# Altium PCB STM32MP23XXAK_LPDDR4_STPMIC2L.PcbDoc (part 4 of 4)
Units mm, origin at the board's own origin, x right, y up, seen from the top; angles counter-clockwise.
Board outline 120 x 79.6 mm, 4 copper layers (Top Layer, Signal Layer 1, Signal Layer 2, Bottom Layer), stack 1.614 mm thick; 156 components, 124 nets, 1131 pads, 692 vias.
Unrouted connection lines stored in the file: 3.
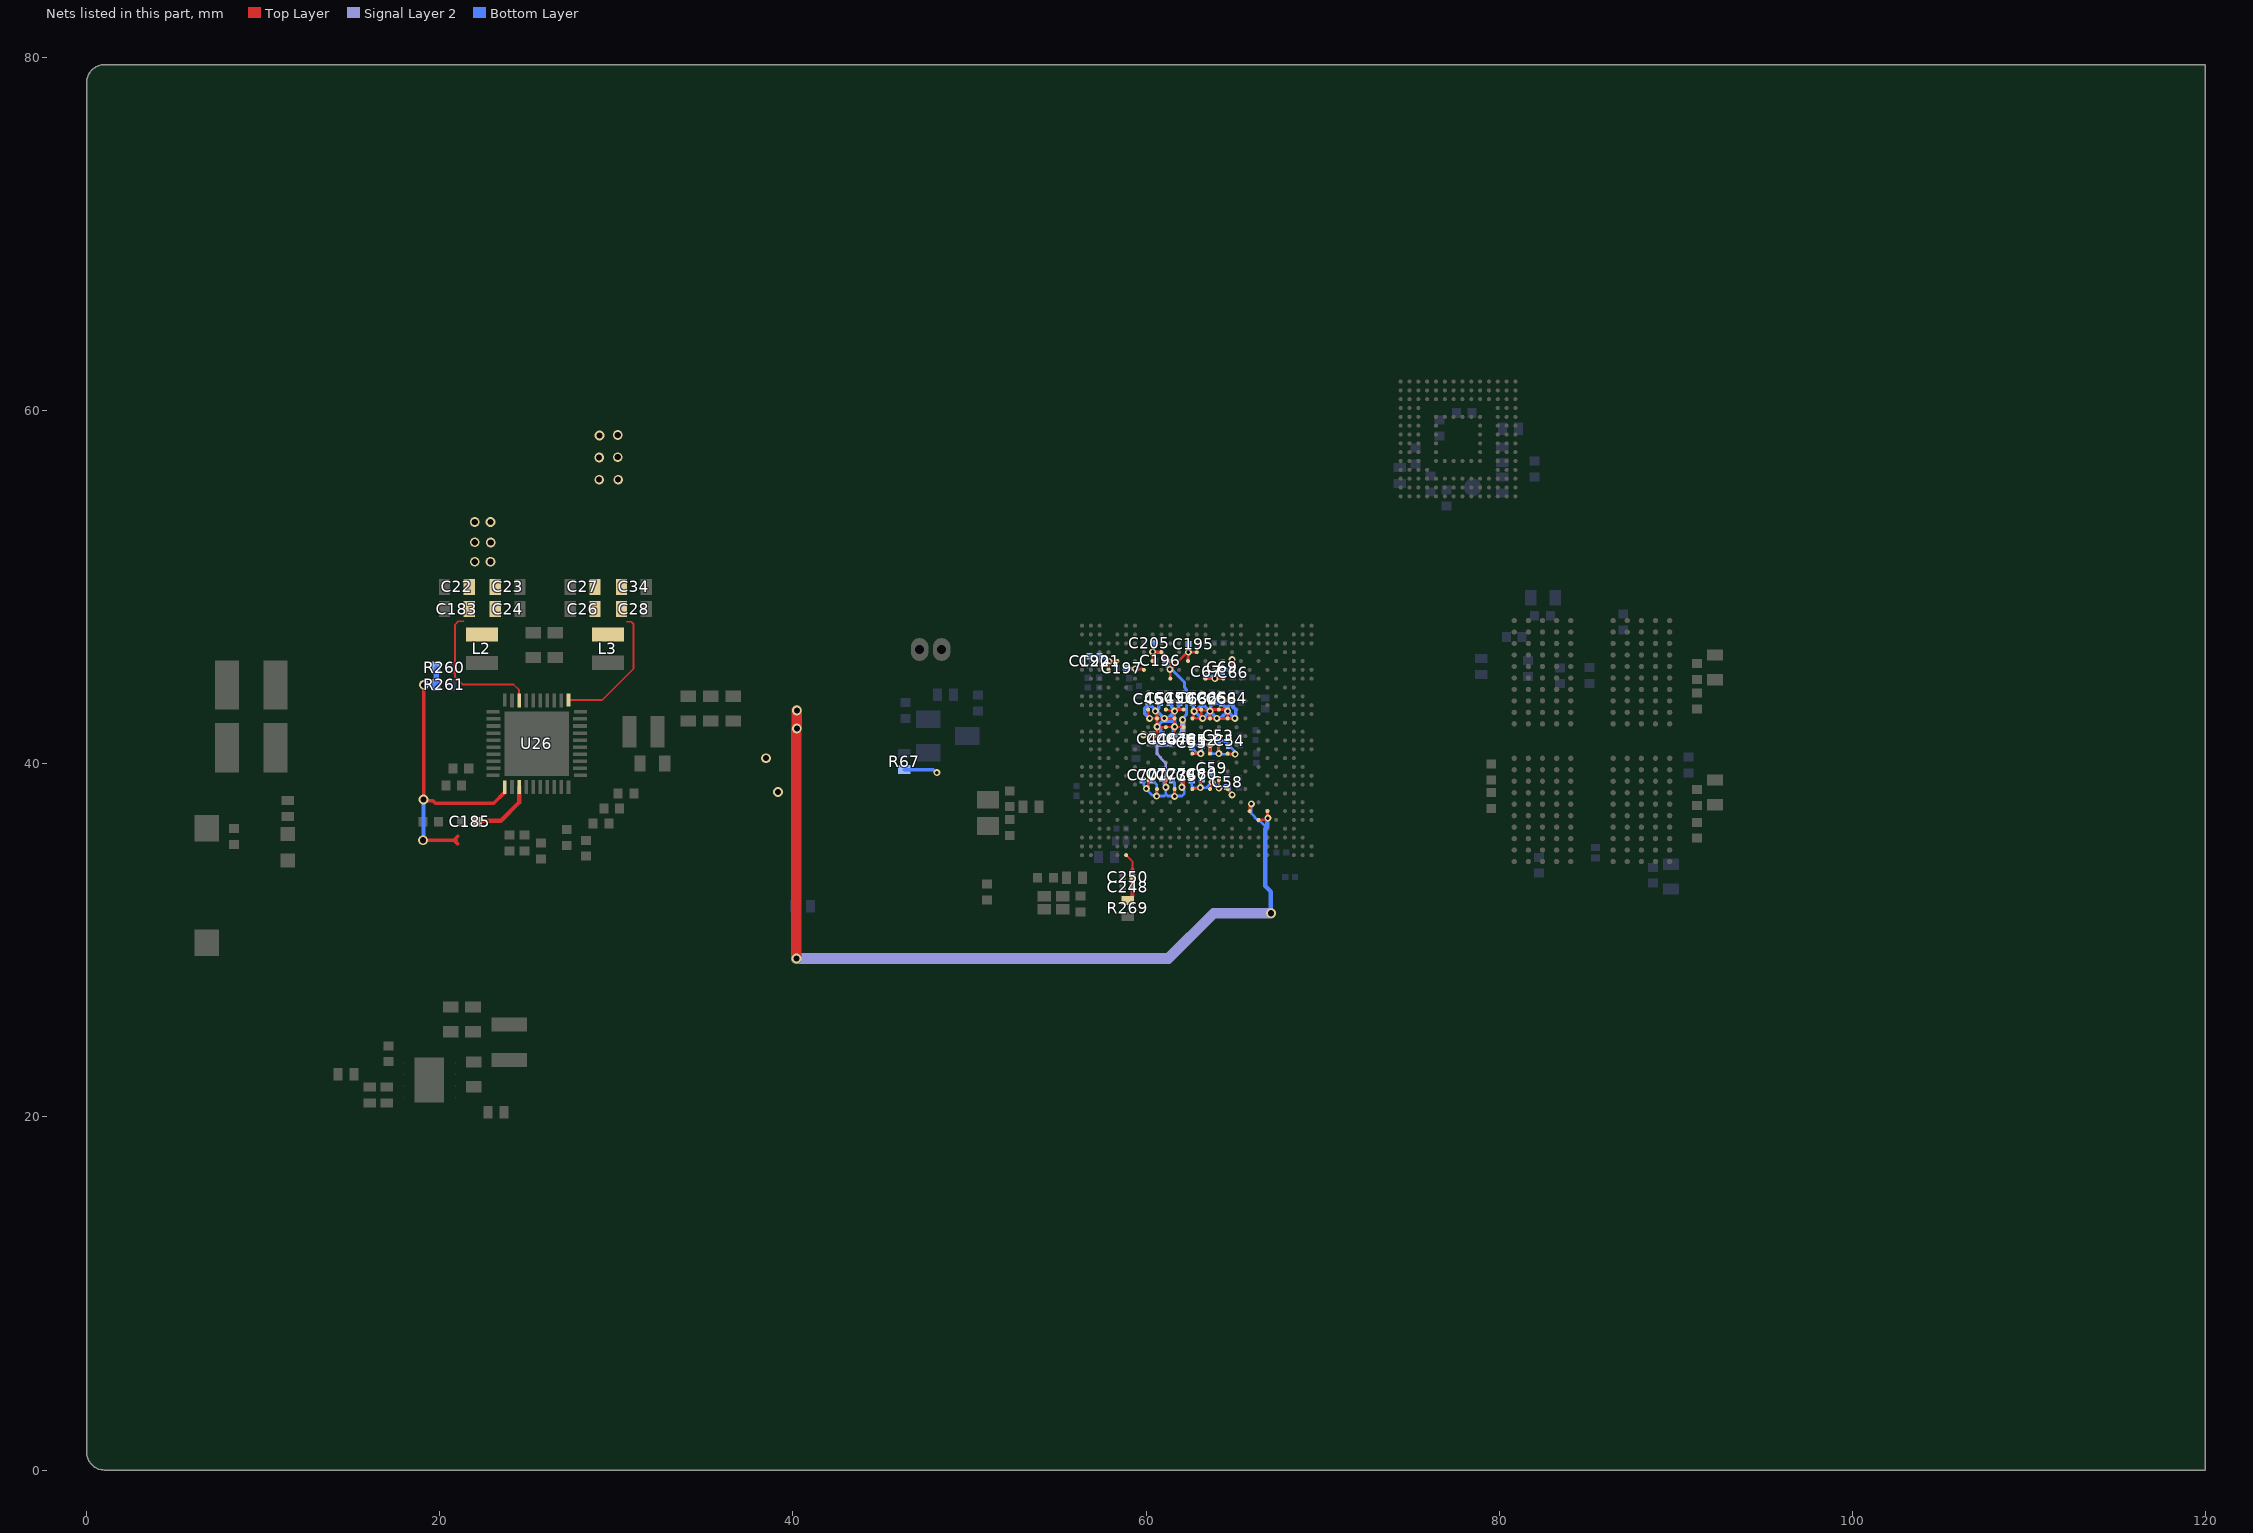
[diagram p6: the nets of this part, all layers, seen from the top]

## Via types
v1: diameter 0.55, hole 0.35, Top Layer to Bottom Layer, 364 vias
v2: diameter 0.4, hole 0.2, Top Layer to Bottom Layer, tented both sides, 223 vias
v3: diameter 0.4, hole 0.2, Top Layer to Bottom Layer, 105 vias

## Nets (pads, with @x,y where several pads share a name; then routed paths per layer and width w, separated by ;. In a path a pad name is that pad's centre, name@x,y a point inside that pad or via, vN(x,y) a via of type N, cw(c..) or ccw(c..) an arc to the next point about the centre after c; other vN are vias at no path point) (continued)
VDDCORE: C22.2 C23.2 C24.2 C44.1 C45.2 C46.2 C47.1 C48.2 C49.2 C50.2 C51.2 C183.2 C192.2 C197.2 C201.2 L2.2 U1.1C1 U1.1C3 U1.1C5 U1.1D2 U1.1D4 U1.1E3 U1.1E5 U1.1F2 U1.1F4 U1.AB20 U1.AB22 U1.AC21 U1.E5 U1.F4 U1.F8 U26.18 | length 80.3
  Top Layer w0.1: 21.35,48.075 21.05,48.075 20.857,47.882 20.857,44.927 21.288,44.495 24.174,44.495 24.488,44.181 U26.18@24.488,43.594
  Top Layer w0.15: U1.F4@57.875,45.325 v2(57.9,45.8) U1.E5@58.375,45.825 ; v2(59.4,45.375) 59.803,45.375 59.853,45.325 U1.F8@59.875,45.325 ; v2(59.85,41.65) 59.904,41.65 59.981,41.573 U1.1F2@60.624,41.573 ; U1.1C1@60.125,43.075 60.125,42.724 60.206,42.643 v2@60.206,42.575 ; v2(60.21,42.575) U1.1D2@60.625,42.575 ; v2@60.545,42.99 60.545,42.922 60.625,42.842 U1.1D2@60.625,42.575 ; U1.1F2@60.625,41.65 v2(60.625,42.1) ; U1.1C3@61.125,43.075 v2(61.625,42.983) ; U1.1F4@61.625,41.575 v2(61.625,42.1) ; U1.1E5@62.125,42.075 v2(61.625,42.1) ; U1.1C5@62.125,43.075 61.771,43.075 61.679,42.983 v2(61.625,42.983) ; U1.AB20@65.875,37.325 65.875,37.607 65.95,37.682 v2@65.95,37.75 ; U1.AC21@66.375,36.825 66.8,36.825 v2@66.888,36.913 ; v2(60.625,42.1) U1.1D2@60.625,42.575 ; v2(60.625,42.1) 60.65,42.075 U1.1E3@61.125,42.075 v2(61.625,42.1) ; U1.1D2@60.625,42.575 61.017,42.572 61.622,42.572 U1.1D4@61.625,42.575 ; v2(61.625,42.1) U1.1D4@61.625,42.575 ; U1.1D4@61.625,42.575 v2@61.625,42.983
  Top Layer w0.16: U1.AB22@66.875,37.325 66.875,36.95 v2(66.9,36.925)
  Top Layer w0.6: v1(40.2,28.975) 40.2,41.975 v1(40.225,42) v1(40.225,43.025)
  Signal Layer 2 w0.6: v1(40.2,28.975) 61.257,28.974 63.827,31.544 66.413,31.544 66.415,31.542 v1(67.078,31.542)
  Bottom Layer w0.15: v2(65.969,37.735) 65.95,37.716 65.95,37.205 66.167,36.988 66.167,36.95 66.367,36.75 66.466,36.75 66.821,36.395
  Bottom Layer w0.2: C192.2@56.8,46.1 C201.2@57.375,46.1 57.45,46.025 57.675,46.025 v2(57.9,45.8) ; C197.2@58.755,45.355 58.775,45.375 v2(59.4,45.375) ; v2(59.85,41.65) 60.346,41.65 C44.1@60.351,41.655 ; v2@60.206,42.575 59.942,42.839 59.942,43.153 60.059,43.27 60.098,43.27 60.173,43.345 60.198,43.32 60.235,43.32 60.285,43.27 60.328,43.27 60.507,43.091 60.507,43.028 60.545,42.99 v2@60.578,42.99 ; C51.2@60.814,43.438 60.788,43.438 60.725,43.375 60.725,43.137 v2@60.578,42.99 ; C46.2@60.84,41.657 C46.2@60.913,41.657 ; C46.2@60.915,41.655 C46.2@60.913,41.657 ; v2@61.135,42.572 61.017,42.572 61.017,42.591 60.719,42.89 60.699,42.89 60.599,42.99 v2@60.578,42.99 ; C49.2@61.377,43.437 61.452,43.362 61.452,43.201 61.625,43.028 v2(61.625,42.983) v2@61.616,42.961 ; C47.1@61.476,41.631 C47.1@61.502,41.657 ; C50.2@61.941,43.438 61.866,43.363 61.866,43.211 v2@61.616,42.961 ; C48.2@62.038,41.657 C47.1@61.502,41.657 ; C46.2@60.913,41.657 C47.1@61.502,41.657 ; C46.2@60.913,41.657 60.84,41.73 60.84,41.94 60.719,42.062 60.663,42.062 v2(60.625,42.1) 60.625,42.107 60.923,42.405 v2@61.06,42.405 ; v2@61.06,42.405 v2@61.227,42.572 ; v2@61.06,42.405 61.623,42.405 ; v2@61.227,42.572 v2@61.616,42.961 ; v2@61.227,42.572 61.455,42.572 ; 61.455,42.572 v2@61.616,42.961 ; 61.455,42.572 61.623,42.405 ; C47.1@61.502,41.657 61.551,41.706 61.551,41.972 61.625,42.046 v2(61.625,42.1) 61.623,42.102 61.623,42.405
  Bottom Layer w0.25: v2(66.9,36.925) 66.875,36.9 66.875,36.449 66.821,36.395 66.75,36.324 66.75,33.083 67.078,32.755 v1(67.078,31.542)
  other v1: 21.975,51.45 22.875,51.45 22.886,52.535 21.975,52.55 21.975,53.7 22.875,53.7
  other v2: 61.04,42.575 60.531,42.99
VDDCPUGPU: C26.2 C27.2 C28.2 C34.2 C52.2 C53.2 C54.2 C55.2 C57.2 C58.2 C59.2 C60.2 C62.1 C63.2 C64.2 C65.1 C66.2 C67.2 C68.2 C69.2 L3.2 U1.1C7 U1.1C9 U1.1D6 U1.1D8 U1.1D10 U1.1G7 U1.1G9 U1.1H6 U1.1H8 U1.1H10 U1.1L7 U1.1L9 U1.1M6 U1.1M8 U1.1M10 U1.F18 U1.G15 U1.G17 U26.11 | length 41.3
  Top Layer w0.1: U26.11@27.288,43.619 29.193,43.619 30.976,45.401 30.976,47.916 30.842,48.05 30.6,48.05 ; U1.1H6@62.625,40.575 U1.1H6@62.625,40.61
  Top Layer w0.125: v2(64.125,40.575) U1.1G9@64.125,41.075
  Top Layer w0.15: U1.1M6@62.625,38.575 v2(63.075,38.65) U1.1L7@63.125,39.075 ; U1.1H6@62.625,40.575 v2(63.1,40.575) ; v2@62.725,42.907 v2@62.725,42.975 ; U1.1G7@63.125,41.075 v2(63.625,41.1) U1.1H8@63.625,40.575 ; v2@63.2,42.575 U1.1D6@62.625,42.575 62.625,42.597 62.696,42.668 62.696,42.956 v2(62.72,42.98) 62.788,42.98 62.883,43.075 U1.1C7@63.125,43.075 ; U1.G15@63.375,44.825 v2(63.9,44.825) U1.G17@64.375,44.825 ; U1.1M8@63.625,38.575 v2(63.747,38.971) ; v2(64.125,38.629) U1.1L9@64.125,39.075 ; U1.1M10@64.625,38.575 v2(64.876,38.245) ; U1.F18@64.875,45.325 v2(64.875,45.91) ; v2@65.017,42.572 64.628,42.572 U1.1D10@64.625,42.575 ; U1.1C7@63.125,43.075 63.125,42.728 63.21,42.643 v2(63.21,42.575) U1.1D8@63.625,42.575 ; U1.1C7@63.125,43.075 v2(63.625,42.983) ; U1.1D8@63.625,42.575 v2(63.625,42.983) ; U1.1D8@63.625,42.575 v2(64.017,42.572) 64.622,42.572 U1.1D10@64.625,42.575 ; v2(63.625,42.983) 63.693,42.983 63.784,43.075 U1.1C9@64.125,43.075 64.466,43.075 64.557,42.983 v2(64.625,42.983) U1.1D10@64.625,42.575
  Top Layer w0.16: U1.1H10@64.625,40.575 v2(65.05,40.55)
  Bottom Layer w0.15: C57.2@62.592,39.053 62.592,38.738 62.68,38.65 v2(63.075,38.65) ; C60.2@63.154,39.122 63.092,39.06 63.092,38.667 v2(63.075,38.65) ; C59.2@63.714,39.486 63.747,39.453 v2(63.747,38.971) ; v2(64.875,45.91) 64.895,45.89 C66.2@64.895,45.441 ; v2(64.876,38.245) 64.876,38.289 64.707,38.458 64.707,38.597 C58.2@64.607,38.697 64.193,38.697 v2(64.125,38.629) 63.783,38.971 v2(63.747,38.971) ; v2(63.075,38.65) 63.426,38.65 v2(63.747,38.971) ; C52.2@63.162,41.057 62.788,41.057 62.756,41.025 62.7,41.025 C55.2@62.6,40.925 62.902,40.623 63.052,40.623 v2(63.1,40.575) 63.162,40.637 C52.2@63.162,41.057 ; C52.2@63.162,41.057 63.184,41.079 63.603,41.079 v2(63.625,41.1) ; v2(63.625,41.1) 63.656,41.131 63.908,41.131 C53.2@64.083,41.306 ; v2(63.625,41.1) 63.625,40.719 63.769,40.575 v2(64.125,40.575) ; C53.2@64.083,41.306 64.396,41.306 64.463,41.239 64.496,41.239 C54.2@64.706,41.029 65.002,40.733 65.002,40.598 v2(65.05,40.55) 64.15,40.55 v2(64.125,40.575) ; C53.2@64.083,41.306 64.083,40.962 64.125,40.919 v2(64.125,40.575)
  Bottom Layer w0.2: C63.2@62.65,43.455 62.685,43.42 v2@62.685,43.015 ; C67.2@63.4,44.95 63.775,44.95 v2(63.9,44.825) 63.933,44.825 64.23,45.122 64.23,45.127 64.3,45.197 C69.2@64.305,45.197 ; v2(64.017,42.572) 64.055,42.61 64.252,42.61 v2(64.625,42.983) ; v2@64.017,42.583 v2@63.625,42.975 ; C69.2@64.305,45.202 64.579,45.324 64.778,45.324 64.886,45.432 64.91,45.423 C66.2@64.915,45.421 ; v2@63.625,42.975 v2(63.625,42.983) ; v2@63.625,42.975 63.625,42.963 63.237,42.575 v2(63.21,42.575) 63.169,42.575 62.764,42.98 v2(62.72,42.98) 62.758,43.018 62.843,43.018 C62.1@63.2,43.375 63.275,43.3 63.308,43.3 v2(63.625,42.983) ; v2(63.625,42.983) 63.625,43.038 63.675,43.088 63.675,43.4 C65.1@63.75,43.475 63.784,43.441 64.284,43.441 C68.2@64.3,43.425 64.587,43.138 64.587,43.022 v2(64.625,42.983) ; v2(64.625,42.983) 64.658,43.016 64.658,43.258 C64.2@64.85,43.45 64.925,43.375 64.925,43.22 65.086,43.059 65.086,42.672 65.04,42.626 v2(65.04,42.572) 65.036,42.572 v2(64.625,42.983)
  other v1: 29.025,56.1 30.1,56.1 29.025,57.35 30.075,57.375 29.05,58.6 30.075,58.625
VDDIO: C70.1 C71.2 C72.2 C73.1 C74.2 C185.1 C195.2 C196.2 C205.2 R67.2 R260.2 R261.2 U1.1L1 U1.1L3 U1.1L5 U1.1M2 U1.1M4 U1.D10 U1.D14 U1.E9 U1.E11 U1.E13 U1.G11 U26.31 U26.33 | length 49
  Top Layer w0.15: v2(60.025,38.6) 60.025,38.618 60.125,38.718 U1.1L1@60.125,39.075 ; U1.E9@60.375,45.825 U1.E9@60.397,45.825 ; U1.E9@60.375,45.825 v2(60.375,46.344) ; v2@60.448,46.335 U1.D10@60.865,46.335 ; v2(60.6,38.175) U1.1M2@60.625,38.575 ; U1.D10@60.875,46.325 60.875,46.322 61,46.197 61,46.17 61.22,45.95 61.247,45.95 61.372,45.825 U1.E11@61.375,45.825 61.375,45.448 61.362,45.435 61.375,45.423 v2@61.375,45.35 ; v2(61.125,38.675) U1.1L3@61.125,39.075 ; v2(61.35,45.35) v2@61.375,45.35 ; U1.G11@61.375,44.825 v2@61.375,45.35 ; U1.1M4@61.625,38.575 61.625,38.212 v2@61.663,38.175 ; v2@62.05,38.675 62.05,38.743 62.125,38.818 U1.1L5@62.125,39.075 ; U1.E13@62.375,45.825 v2(62.4,46.325) ; U1.D14@62.875,46.325 v2(62.4,46.325) ; v2@61.375,45.35 61.388,45.35 62.363,46.325 v2(62.4,46.325)
  Top Layer w0.2: v1(19.05,35.675) 20.8,35.675 ; v1(19.1,44.475) 19.088,44.463 19.088,37.987 v1(19.075,37.975) 19.142,37.908 19.611,37.908 19.75,37.769 23.054,37.769 U26.31@23.663,38.378 ; 20.935,35.675 20.8,35.675 ; 21,35.475 20.8,35.675 ; 21.025,35.9 20.8,35.675
  Top Layer w0.25: C185.1@22.088,36.764 22.713,36.764 22.718,36.769 23.444,36.769 24.488,37.812 U26.33@24.488,38.694
  Signal Layer 2 w0.15: 60.633,41.112 60.619,41.098 60.619,40.581 60.827,40.373 60.827,40.328 61.125,40.03 v2(61.125,38.675)
  Signal Layer 2 w0.3: 60.633,41.112 60.859,41.112 ; 60.885,41.138 61.426,41.138 62.075,41.787 62.075,42.494 v2(62.072,42.497) v2@62.072,42.36
  Bottom Layer w0.15: C70.1@59.781,39.075 59.881,38.975 59.881,38.787 60.025,38.643 v2(60.025,38.6) 60.025,38.55 60.352,38.223 60.552,38.223 v2(60.6,38.175) ; C71.2@60.34,39.085 60.6,38.825 v2(60.6,38.175) ; C72.2@60.905,39.148 61.005,39.048 61.005,38.863 61.125,38.743 v2(61.125,38.675) 61.125,38.285 ; C73.1@61.467,39.074 61.61,38.931 v2@61.61,38.175 ; v2(61.625,38.16) v2@61.61,38.175 ; C74.2@62.03,39.133 62.04,39.123 62.04,38.685 62.05,38.675 62.05,38.607 62.175,38.482 62.175,38.323 62.027,38.175 v2@61.61,38.175 ; v2(60.6,38.175) 61.037,38.175 61.125,38.263 61.125,38.285 ; 61.125,38.285 61.235,38.175 v2@61.61,38.175
  Bottom Layer w0.175: C205.2@60.452,46.829 60.389,46.765 v2@60.389,46.357 ; v2@60.485,46.38 60.411,46.38 v2@60.389,46.357 ; v2@61.35,45.366 61.35,45.39 61.175,45.565 61.175,45.66 61.163,45.672 61.163,45.762 C196.2@61.075,45.85 61,45.925 61,46.01 60.968,46.042 60.968,46.188 60.85,46.305 60.413,46.305 v2(60.375,46.344) v2@60.389,46.357 ; v2@61.362,45.435 62.186,44.612 62.186,44.315 62.253,44.249 62.253,44.231 62.283,44.2 62.283,42.776 62.072,42.564 v2(62.072,42.497)
  Bottom Layer w0.2: v1(19.05,35.675) 19.075,35.7 v1(19.075,37.975) ; v1(19.1,44.475) 19.638,44.475 R261.2@19.7,44.413 ; R67.2@46.3,39.675 47.941,39.675 48.116,39.5 v2(48.158,39.5) ; v2(62.4,46.325) C195.2@62.4,46.787
  Bottom Layer w0.3: R261.2@19.785,44.474 19.796,44.464 R260.2@19.796,45.439
  other v1: 39.15,38.4 38.475,40.325
  other v2: 62.03,38.675
VREF+: C248.2 C250.2 R269.2 U1.AG6 | length 2.9
  Top Layer w0.09: U1.AG6@58.875,34.825 59.13,34.57
  Top Layer w0.1: 59.13,34.57 59.233,34.467 59.233,34.02
  Top Layer w0.25: R269.2@58.956,32.258 59.051,32.258 59.181,32.388 59.181,32.483 59.233,32.535 C248.2@59.233,33.002 C250.2@59.233,33.572 59.233,34.02
pads on no net: U1.A3 U1.A6 U1.A7 U1.A10 U1.A11 U1.A14 U1.A15 U1.A18 U1.A19 U1.A26 U1.AA3 U1.AA5 U1.AA7 U1.AA9 U1.AA11 U1.AA13 U1.AA15 U1.AA17 U1.AA19 U1.AA21 U1.AA23 U1.AB1 U1.AB2 U1.AB8 U1.AB10 U1.AB12 U1.AB14 U1.AB16 U1.AB18 U1.AB24 U1.AC2 U1.AC7 U1.AC9 U1.AC13 U1.AC15 U1.AC17 U1.AC19 U1.AC23 U1.AC25 U1.AD4 U1.AD6 U1.AD8 U1.AD10 U1.AD12 U1.AD14 U1.AD16 U1.AD18 U1.AD20 U1.AD24 U1.AD25 U1.AE2 U1.AE3 U1.AE4 U1.AE5 U1.AE6 U1.AE7 U1.AE8 U1.AE9 U1.AE10 U1.AE11 U1.AE12 U1.AE13 U1.AE14 U1.AE15 U1.AE16 U1.AE17 U1.AE18 U1.AE19 U1.AE20 U1.AE24 U1.AE25 U1.AE26 U1.AF1 U1.AF3 U1.AF7 U1.AF9 U1.AF10 U1.AF11 U1.AF13 U1.AF14 U1.AF15 U1.AF17 U1.AF18 U1.AF19 U1.AF21 U1.AF22 U1.AF23 U1.AF25 U1.AF26 U1.AF27 U1.AG5 U1.AG9 U1.AG10 U1.AG13 U1.AG14 U1.AG17 U1.AG18 U1.AG21 U1.AG22 U1.AG25 U1.AG26 U1.B1 U1.B2 U1.B3 U1.B5 U1.B6 U1.B7 U1.B9 U1.B10 U1.B11 U1.B13 U1.B14 U1.B15 U1.B17 U1.B18 U1.B19 U1.B21 U1.B26 U1.B27 U1.C2 U1.C3 U1.C4 U1.C5 U1.C7 U1.C8 U1.C9 U1.C11 U1.C12 U1.C13 U1.C14 U1.C15 U1.C16 U1.C17 U1.C18 U1.C19 U1.C20 U1.C21 U1.C22 U1.C26 U1.C27 U1.D3 U1.D4 U1.D6 U1.D8 U1.D12 U1.D16 U1.D20 U1.D25 U1.E1 U1.E2 U1.E3 U1.F1 U1.F2 U1.F6 U1.F10 U1.G2 U1.G3 U1.G13 U1.G21 U1.H3 U1.H4 U1.J1 U1.J2 U1.J3 U1.J5 U1.K1 U1.K2 U1.K4 U1.K6 U1.K24 U1.L2 U1.L3 U1.L5 U1.L7 U1.L21 U1.M3 U1.M4 U1.M6 U1.N1 U1.N2 U1.N3 U1.N5 U1.N7 U1.P1 U1.P2 U1.P3 U1.P4 U1.P6 U1.R2 U1.R3 U1.R5 U1.T3 U1.T4 U1.U1 U1.U2 U1.U3 U1.U5 U1.U7 U1.V1 U1.V2 U1.V3 U1.V4 U1.W5 U1.W7 U1.W21 U1.W23 U1.Y3 U1.Y6 U1.Y22 U2.A1 U2.A2 U2.A8 U2.A11 U2.A12 U2.AA1 U2.AA12 U2.AB1 U2.AB2 U2.AB11 U2.AB12 U2.B1 U2.B12 U2.G11 U2.H3 U2.J5 U2.K5 U2.K8 U2.N5 U2.N8 U2.P5 U2.R3 U26.24 U26.25 U26.26 U26.27 U37.A1 U37.A2 U37.A7 U37.A8 U37.A9 U37.A10 U37.A11 U37.A12 U37.A13 U37.A14 U37.B1 U37.B7 U37.B8 U37.B9 U37.B10 U37.B11 U37.B12 U37.B13 U37.B14 U37.C1 U37.C3 U37.C5 U37.C7 U37.C8 U37.C9 U37.C10 U37.C11 U37.C12 U37.C13 U37.C14 U37.D1 U37.D2 U37.D3 U37.D4 U37.D12 U37.D13 U37.D14 U37.E1 U37.E2 U37.E3 U37.E5 U37.E8 U37.E9 U37.E10 U37.E12 U37.E13 U37.E14 U37.F1 U37.F2 U37.F3 U37.F10 U37.F12 U37.F13 U37.F14 U37.G1 U37.G2 U37.G3 U37.G10 U37.G12 U37.G13 U37.G14 U37.H1 U37.H2 U37.H3 U37.H12 U37.H13 U37.H14 U37.J1 U37.J2 U37.J3 U37.J12 U37.J13 U37.J14 U37.K1 U37.K2 U37.K3 U37.K6 U37.K7 U37.K10 U37.K12 U37.K13 U37.K14 U37.L1 U37.L2 U37.L3 U37.L12 U37.L13 U37.L14 U37.M1 U37.M2 U37.M3 U37.M7 U37.M8 U37.M9 U37.M10 U37.M11 U37.M12 U37.M13 U37.M14 U37.N1 U37.N3 U37.N6 U37.N7 U37.N8 U37.N9 U37.N10 U37.N11 U37.N12 U37.N13 U37.N14 U37.P1 U37.P2 U37.P7 U37.P8 U37.P9 U37.P10 U37.P11 U37.P12 U37.P13 U37.P14
copper on no net: | length 1428.3
  Top Layer w0.09: 39.873,56.227 53.275,42.825 56.875,42.825 ; 39.977,56.477 53.378,43.075 57.123,43.075 57.373,42.825 57.375,42.825 ; 40.175,57 53.85,43.325 56.375,43.325 ; 40.279,57.25 53.954,43.575 56.604,43.575 56.854,43.325 56.875,43.325 ; 40.575,57.875 54.625,43.825 56.375,43.825 ; 40.679,58.125 54.729,44.075 56.625,44.075 56.875,43.825 ; 40.8,58.825 55.301,44.324 57.374,44.324 ; 40.904,59.075 55.398,44.581 57.619,44.581 57.875,44.325 ; 40.925,59.8 55.9,44.825 56.875,44.825 ; 41.028,60.049 56.002,45.075 57.104,45.075 57.354,44.825 57.375,44.825 ; 41.372,60.697 53.744,48.325 56.941,48.325 57.105,48.161 57.105,47.949 57.125,47.929 57.125,47.575 57.373,47.327 57.375,47.327 ; 41.476,60.947 53.848,48.575 57.045,48.575 57.355,48.265 57.355,48.052 57.375,48.032 57.375,47.825 ; 41.622,61.627 54.147,49.101 57.05,49.101 57.625,48.526 57.625,46.575 57.875,46.325 ; 41.725,61.877 54.251,49.351 57.153,49.351 57.815,48.69 57.815,47.025 57.859,46.879 57.875,46.825 ; 41.962,62.567 54.586,49.943 57.188,49.943 58.005,49.126 58.005,47.232 58.375,46.862 58.375,46.825 ; 42.065,62.817 54.689,50.193 57.291,50.193 58.225,49.259 58.225,47.478 58.375,47.328 58.375,47.325 ; 47.601,58.348 55.092,50.857 57.854,50.857 58.65,50.061 58.65,48.127 58.625,48.102 58.625,47.721 58.86,47.486 58.86,47.34 58.875,47.325 ; 48.037,59.122 55.493,51.666 58.113,51.666 59.091,50.688 59.091,47.963 59.125,47.929 59.125,47.575 59.375,47.325 ; 48.141,59.372 55.597,51.916 58.216,51.916 59.341,50.792 59.341,48.066 59.375,48.032 59.375,47.825 ; 48.241,58.062 55.196,51.107 57.958,51.107 58.9,50.165 58.9,48.024 58.875,47.999 58.875,47.825 ; 51.21,57.126 53.846,54.489 55.788,52.548 58.415,52.548 59.531,51.432 59.531,48.2 59.695,48.036 59.695,47.752 59.625,47.682 59.625,47.174 59.625,47.073 59.377,46.825 59.375,46.825 ; 51.386,57.303 54.023,54.666 55.891,52.798 58.519,52.798 59.781,51.536 59.781,48.304 59.945,48.14 59.945,47.649 59.875,47.579 59.875,47.07 59.875,46.825 ; 53.528,34.458 53.958,34.888 54.709,34.888 55.078,35.258 55.53,35.258 55.847,35.575 56.979,35.575 57.125,35.721 57.125,35.736 57.188,35.798 57.348,35.798 57.375,35.825 ; 55.62,35.07 55.875,35.325 56.375,35.325 ; 55.625,36.655 56.67,36.655 56.84,36.825 56.875,36.825 ; 55.625,36.869 56.566,36.869 56.771,37.075 56.979,37.075 57.125,37.221 57.125,37.575 57.375,37.825 ; 55.625,37.075 56.479,37.075 56.702,37.298 56.848,37.298 56.875,37.325 ; 55.625,39.294 55.905,39.294 56.123,39.075 56.479,39.075 56.715,39.311 56.861,39.311 56.875,39.325 ; 55.625,39.494 55.959,39.494 56.128,39.325 56.375,39.325 ; v2@55.625,40.075 56.625,40.075 56.875,39.825 ; 55.625,40.42 55.648,40.42 55.793,40.275 56.68,40.275 56.73,40.325 57.375,40.325 ; 55.625,41.075 55.897,41.075 56.087,40.885 56.543,40.885 56.733,41.075 57.125,41.075 57.375,41.325 ; 55.625,41.494 56.038,41.494 56.182,41.35 56.35,41.35 56.375,41.325 ; 55.625,41.694 56.153,41.694 56.271,41.575 56.625,41.575 56.875,41.825 ; 55.625,41.894 56.207,41.894 56.251,41.85 56.35,41.85 56.375,41.825 ; 55.625,42.094 57.123,42.094 57.141,42.075 57.491,42.075 57.721,42.305 57.855,42.305 57.875,42.325 ; 55.625,42.294 57.252,42.294 57.257,42.298 57.348,42.298 57.375,42.325 ; 55.625,42.494 57.063,42.494 57.144,42.575 58.125,42.575 58.375,42.825 ; 55.92,36.07 55.925,36.075 56.625,36.075 56.875,35.825 ; 56.082,53.397 58.764,53.397 60.225,51.936 60.225,49.675 59.995,49.445 59.995,48.575 59.995,48.344 60.068,48.271 60.125,48.214 60.125,47.429 60.125,47.075 60.375,46.825 ; 56.114,38.255 57.267,38.255 57.337,38.325 57.375,38.325 ; 56.166,40.7 56.747,40.7 56.872,40.825 56.875,40.825 ; 56.183,38.89 56.188,38.895 56.553,38.895 56.733,39.075 57.125,39.075 57.374,39.324 ; 56.185,53.647 58.868,53.647 60.475,52.04 60.475,49.571 60.245,49.341 60.245,48.575 60.245,48.448 60.375,48.318 60.375,47.325 ; 56.195,41.075 56.479,41.075 56.702,41.298 56.848,41.298 56.875,41.325 ; 56.264,39.575 56.271,39.575 57.125,39.575 57.375,39.825 ; 56.279,54.255 59.174,54.255 60.9,52.529 60.9,49.45 60.53,49.08 60.53,48.575 60.53,48.529 60.625,48.434 60.625,47.575 60.875,47.325 ; 56.382,54.505 59.278,54.505 61.15,52.633 61.15,49.346 60.78,48.976 60.78,48.632 60.875,48.537 60.875,47.825 ; 56.655,40.505 57.055,40.505 57.375,40.825 ; 57.125,34.075 57.125,35.429 57.271,35.575 57.479,35.575 57.625,35.721 57.625,36.075 57.875,36.325 ; 57.325,34.075 57.325,34.605 57.375,34.655 57.375,35.325 ; 57.525,34.075 57.525,34.441 57.585,34.501 57.585,35.152 57.625,35.192 57.625,35.467 57.848,35.69 57.848,35.798 57.875,35.825 ; 57.76,34.344 57.765,34.349 57.765,35.078 57.805,35.118 57.805,35.363 58.24,35.798 58.348,35.798 58.375,35.825 ; v2@57.775,39.875 57.775,40.187 57.875,40.287 57.875,40.325 ; v2(57.79,38.85) 57.79,39.202 57.875,39.287 57.875,39.325 ; v2@57.9,41.825 58.375,41.825 ; 57.925,34.075 57.925,34.16 57.945,34.18 57.945,35.003 57.985,35.043 57.985,35.289 58.271,35.575 58.525,35.575 58.625,35.675 58.625,36.075 58.875,36.325 ; v2(58.349,38.315) 58.375,38.341 58.375,38.825 ; v2(58.375,37.35) 58.375,37.825 ; 58.375,43.825 58.388,43.813 58.862,43.813 v2@58.875,43.8 ; v2@58.391,42.3 58.416,42.325 58.875,42.325 ; v2@58.858,40.933 58.877,40.952 58.877,41.323 58.875,41.325 ; 58.875,35.825 59.125,35.575 59.125,35.104 ; 58.875,38.325 58.928,37.865 v2(58.939,37.77) ; v2@58.875,42.8 58.875,43.325 ; 59.375,38.825 59.375,38.802 59.475,38.702 v2(59.475,38.325) ; v2(59.45,46.325) 59.875,46.325 ; 59.625,35.629 59.625,36.075 59.875,36.325 ; 59.925,34.442 59.925,35.225 60.125,35.425 60.125,36.125 60.375,36.375 60.375,36.825 ; 60.125,34.59 60.125,35.075 60.375,35.325 ; 60.473,34.569 60.625,34.721 60.625,36.075 60.875,36.325 ; 60.679,34.372 60.875,34.568 60.875,34.825 ; 60.875,35.325 61.125,35.075 61.125,34.485 ; 61.375,34.075 61.375,35.325 ; 61.375,35.825 61.625,35.575 61.625,35.221 61.605,35.201 61.605,34.075 ; 61.375,46.825 61.765,47.215 61.765,47.607 61.826,47.668 61.826,48.429 61.972,48.575 ; 61.375,47.325 61.585,47.535 61.585,47.681 61.625,47.721 61.625,48.504 61.85,48.729 61.85,48.875 ; 61.88,46.83 61.895,46.845 61.895,47.09 61.945,47.14 61.945,47.532 62.065,47.652 62.065,48.407 62.233,48.575 ; 62.1,34.075 62.1,35.05 62.375,35.325 ; 62.362,34.075 62.362,34.812 62.375,34.825 ; 62.375,35.825 62.625,35.575 62.625,34.075 ; 62.375,46.825 62.125,47.075 62.125,47.458 62.265,47.598 62.265,48.345 62.45,48.53 62.45,48.575 ; 62.375,47.325 62.4,47.35 62.4,47.478 62.445,47.523 62.445,48.271 62.65,48.476 62.65,48.575 ; 62.85,48.575 62.85,48.421 62.625,48.196 62.625,47.075 62.875,46.825 ; 62.875,35.325 62.898,35.302 62.898,35.156 63.125,34.929 63.125,34.164 63.085,34.124 63.085,34.075 ; 62.875,35.825 63.125,35.575 63.125,35.221 63.305,35.041 63.305,34.075 ; 62.875,36.325 63.146,36.325 63.162,36.309 63.316,36.309 v2@63.375,36.25 ; v2@62.875,37.725 62.959,37.725 63.059,37.825 63.375,37.825 ; 62.875,47.325 63.125,47.575 63.125,48.17 63.251,48.297 63.251,48.575 ; 62.875,47.825 62.875,48.175 63.05,48.35 63.05,48.575 ; 63.375,35.318 63.375,35.293 63.515,35.153 63.515,34.075 ; 63.375,35.825 63.695,35.505 63.695,34.164 63.725,34.134 63.725,34.075 ; 63.375,46.825 63.825,47.275 ; 63.375,47.325 63.65,47.6 63.65,48.575 ; 63.875,35.825 63.875,35.334 63.945,35.264 63.945,34.647 63.949,34.643 63.949,34.075 ; 63.875,46.825 63.875,46.85 64.05,47.025 64.05,48.575 ; 64.154,34.075 64.154,34.693 64.125,34.721 64.125,35.075 64.375,35.325 ; 64.375,34.075 64.375,34.825 ; 64.375,35.825 64.625,35.575 64.625,34.635 ; 64.375,46.825 64.625,47.075 64.625,47.838 64.451,48.012 64.451,48.575 ; 64.851,48.575 64.851,48.203 65.125,47.929 65.125,47.075 64.875,46.825 ; 64.875,35.325 64.889,35.311 64.889,35.165 65.125,34.929 65.125,34.486 65.075,34.436 65.075,34.075 ; 64.875,35.825 65.125,35.575 65.125,35.183 65.305,35.003 65.305,34.411 65.29,34.396 65.29,34.085 65.28,34.075 65.275,34.07 65.275,34.04 ; 65.051,48.575 65.051,48.257 65.305,48.003 65.305,47.933 65.375,47.863 65.375,47.825 ; 65.375,35.325 65.375,35.29 65.485,35.18 65.485,34.08 65.48,34.075 ; 65.375,35.825 65.675,35.525 65.675,34.075 65.675,33.925 ; 65.375,46.825 65.625,47.075 65.625,47.229 65.695,47.299 65.695,47.537 65.805,47.647 65.805,48.166 65.63,48.342 65.63,48.575 ; 65.375,47.325 65.515,47.465 65.515,47.611 65.625,47.721 65.625,48.015 65.375,48.265 ; 65.875,34.075 65.875,35.825 ; 65.875,46.825 65.875,47.462 65.985,47.572 65.985,48.267 65.875,48.377 65.875,48.575 ; 66.115,47.085 66.115,47.434 66.175,47.494 66.175,48.356 66.125,48.406 66.125,48.575 66.125,48.615 ; 66.625,34.714 66.625,34.936 ; v2@67.961,36.833 68.206,36.589 68.206,36.517 68.377,36.347 68.377,36.333 ; 68.375,36.825 ccw(c68.39,36.914) 68.379,36.824 68.444,36.816 v2(68.85,36.41) ; 68.375,46.325 68.413,46.325 68.48,46.392 68.579,46.392 68.724,46.537 68.94,46.537 69.125,46.721 69.125,46.825 69.125,46.929 69.271,47.075 69.511,47.075 69.809,47.373 69.841,47.373 ; 68.875,46.825 68.875,46.995 69.125,47.245 69.125,47.429 69.271,47.575 69.487,47.575 69.805,47.893 69.905,47.893 70.207,48.194 70.207,48.549 ; 68.889,47.339 68.889,47.485 69.125,47.721 69.125,48.118 69.582,48.575 ; 69.375,46.825 69.673,46.825 70.78,47.932 ; 69.375,47.325 69.398,47.348 69.529,47.348 69.884,47.703 70.012,47.703 70.51,48.2
  Top Layer w0.091: 65.475,33.994 65.475,34.001 65.48,34.006 65.48,34.075
  Top Layer w0.097: 63.65,48.575 63.65,48.681
  Top Layer w0.1: 39.879,55.293 41.683,53.488 41.683,53.37 44.316,50.738 44.316,47.708 46.24,45.785 46.24,42.779 44.461,41 v2(44.43,41) ; v2(43.9,37.12) 44.218,37.438 44.218,39.273 47.239,42.294 55.625,42.294 ; v2(44.4,37.12) 44.447,37.167 44.447,39.026 47.514,42.094 55.625,42.094 ; v2(44.8,38.125) 44.8,38.939 47.434,41.573 50.112,41.573 50.866,40.82 53.566,40.82 54.04,41.294 55.977,41.294 56.195,41.075 ; v2(45.3,38.125) 45.3,38.979 47.694,41.373 50.03,41.373 50.8,40.603 53.632,40.603 54.104,41.075 55.625,41.075 ; v2(45.8,38.125) 45.8,39.096 47.877,41.173 49.947,41.173 50.718,40.403 53.715,40.403 54.187,40.875 55.782,40.875 55.957,40.7 56.166,40.7 ; v2(45.825,36.825) 45.825,37.441 46.187,37.803 46.187,39.02 48.141,40.973 49.864,40.973 50.635,40.203 53.798,40.203 54.215,40.62 55.746,40.62 55.861,40.505 56.655,40.505 ; v2(46.325,36.825) 46.382,36.882 46.382,37.348 46.591,37.557 46.591,38.953 48.411,40.773 49.781,40.773 50.561,39.994 53.329,39.994 53.629,39.694 56.021,39.694 56.139,39.575 56.264,39.575 ; v2@46.875,36.833 46.875,38.78 48.669,40.573 49.698,40.573 50.478,39.794 53.247,39.794 53.546,39.494 55.625,39.494 ; v1(48.806,33.855) 50.209,35.258 53.188,35.258 53.573,35.643 54.396,35.643 54.727,35.974 54.727,36.37 55.012,36.655 55.625,36.655 ; v2(49.358,39.866) 49.83,39.394 50.019,39.394 50.021,39.392 50.476,39.392 50.478,39.394 53.081,39.394 53.381,39.094 55.843,39.094 56.047,38.89 56.183,38.89 ; v2(49.475,38.554) 49.913,38.992 50.642,38.992 50.644,38.994 52.847,38.994 53.391,38.45 54.448,38.45 54.704,38.194 55.16,38.194 55.402,38.435 55.695,38.435 55.875,38.255 56.114,38.255 ; 49.692,35.458 53.105,35.458 53.501,35.854 54.306,35.854 54.527,36.074 54.527,36.453 54.943,36.869 55.625,36.869 ; v2(49.889,39.866) 50.162,39.594 53.164,39.594 53.464,39.294 55.625,39.294 ; v1(50.389,33.869) 50.482,33.869 51.471,34.858 53.36,34.858 53.765,35.263 54.553,35.263 54.939,35.648 55.355,35.648 55.777,36.07 55.92,36.07 ; v1(51.631,33.875) 52.214,34.458 53.528,34.458 ; v2(52.031,42.8) 52.337,42.494 55.625,42.494 ; v2(52.175,41.475) 52.525,41.125 52.849,41.125 53.417,41.694 55.625,41.694 ; v2(52.675,41.475) 53.094,41.894 55.625,41.894 ; 52.871,34.268 53.617,34.268 54.052,34.703 54.372,34.703 54.785,34.703 55.152,35.07 55.62,35.07 ; v2(53.389,41.17) 53.712,41.494 55.625,41.494 ; v2(53.45,36.225) 53.9,36.675 54.139,36.675 54.789,37.325 56.375,37.325 ; 54.014,29.76 55.661,29.76 56.837,30.936 56.837,31.895 57.325,32.383 57.325,34.075 ; v2(54.175,36.225) 54.175,36.384 54.866,37.075 55.625,37.075 ; v2(54.436,40.077) 54.779,40.42 55.625,40.42 ; v2(55.458,40.07) 55.463,40.075 v2@55.625,40.075 ; v2(56.956,32.51) 56.956,32.865 57.125,33.033 57.125,34.075 ; v2(57.271,30.195) 57.925,30.848 57.925,34.075 ; v2(57.271,30.982) 57.725,31.436 57.725,34.309 57.76,34.344 ; v2(57.275,31.8) 57.525,32.05 57.525,34.075 ; 57.375,43.825 57.77,43.825 v2(57.782,43.813) ; v2(57.79,40.85) 57.816,40.825 58.375,40.825 ; 57.875,41.325 57.899,41.325 57.999,41.425 v2@58.35,41.425 ; 57.875,43.325 v2(58.348,43.3) ; 58.325,30.282 58.325,33.533 58.325,34.354 58.375,34.404 58.375,34.825 ; v2(58.325,39.355) 58.375,39.405 58.375,39.825 ; v2(58.396,46.369) 58.875,46.325 ; v2(58.875,41.75) 58.932,41.807 59.039,41.807 59.056,41.825 59.375,41.825 ; 58.875,45.325 v2(58.875,45.9) ; 59.125,35.104 59.454,34.775 59.454,34.234 59.623,34.064 59.623,31.68 59.778,31.525 59.778,31.178 v2(59.781,31.175) ; v2@59.272,42.372 59.272,42.453 59.375,42.556 59.375,42.825 ; v2@59.3,39.367 59.316,39.465 59.375,39.825 ; v2(59.469,37.256) 59.802,37.313 59.875,37.325 ; 59.625,35.629 59.729,35.525 59.729,34.27 59.823,34.176 59.823,32.01 60.395,31.439 60.395,30.77 v2(60.375,30.75) ; 59.925,34.442 60.023,34.344 60.023,32.093 60.451,31.666 60.469,31.666 v2(60.96,31.175) ; 60.125,34.59 60.223,34.492 60.223,32.412 60.408,32.228 v2(60.408,32.204) ; v2@60.375,45.325 60.875,45.325 ; 60.473,34.569 60.423,34.52 60.423,32.746 v2(60.96,32.21) ; 60.679,34.372 60.623,34.316 60.623,33.097 v2(60.956,32.765) ; v2(60.973,33.601) 60.973,34.333 61.125,34.485 ; 61.225,54.759 62.25,53.734 62.25,48.594 62.233,48.577 62.233,48.575 ; 61.301,54.4 62.05,53.651 62.05,48.677 62.045,48.672 62.045,48.648 61.972,48.575 ; 61.325,53.425 61.637,53.113 61.637,48.792 61.375,48.53 61.375,47.825 ; v2(61.375,46.325) 61.875,46.325 ; 61.389,53.962 61.85,53.501 61.85,48.875 ; 61.65,54.617 62.45,53.817 62.45,48.575 ; 62.075,54.475 62.65,53.9 62.65,48.575 ; 62.375,44.825 v2(62.375,45.3) ; 62.649,54.184 62.85,53.983 62.85,48.575 ; 63.05,48.575 63.05,54.753 ; 63.25,55.155 63.25,48.576 63.251,48.575 ; 63.375,36.825 63.381,36.831 63.819,36.831 v2@63.875,36.775 ; v2@63.375,37.275 63.425,37.325 63.875,37.325 ; 63.375,47.825 63.375,48.159 63.451,48.235 63.451,48.575 63.451,48.597 63.45,48.598 63.45,55.572 ; 63.65,48.681 63.65,55.856 ; 63.825,47.275 63.85,47.3 63.85,48.575 63.85,56.423 ; 63.875,36.325 64.219,36.271 64.354,36.271 v2@64.375,36.25 ; v2(63.9,37.925) 63.94,37.885 64.055,37.885 64.375,37.825 ; 63.949,34.075 63.949,30.385 63.945,30.382 63.945,29.105 64.017,29.033 64.017,28.387 ; 64.05,48.575 64.05,56.294 ; 64.251,55.893 64.251,47.763 64.375,47.638 64.375,47.325 ; 64.375,34.075 64.375,29.626 64.904,29.097 64.904,28.387 ; 64.375,36.825 64.379,36.829 64.379,37.346 v2(64.375,37.35) ; 64.451,48.575 64.451,55.733 ; 64.625,34.635 64.625,29.701 65.331,28.995 65.331,28.141 65.5,27.973 65.5,26.55 ; 64.651,55.281 64.651,48.074 64.875,47.85 64.875,47.825 ; v2(64.8,37.75) 64.875,37.325 ; 64.851,48.575 64.851,54.9 65.325,55.374 ; 64.875,34.825 64.875,32.955 64.849,32.929 64.849,29.81 65.531,29.128 65.531,28.224 65.956,27.799 65.956,26.206 65.462,25.712 65.01,25.712 ; 64.875,36.325 v2(64.875,36.829) ; 65.051,48.575 65.051,54.817 65.525,55.291 ; 65.075,34.075 65.075,32.872 65.049,32.846 65.049,29.893 v2(65.956,28.986) ; 65.275,34.04 65.275,32.41 65.249,32.384 65.249,30.526 v2(65.5,30.275) ; v2@65.375,36.275 65.375,36.825 ; 65.375,37.825 65.55,37.65 65.55,37.174 65.74,36.985 65.74,36.76 v2@65.775,36.725 ; 65.475,33.994 65.475,32.327 65.449,32.301 65.449,30.993 66.003,30.439 v2(66.003,29.72) ; 65.675,33.925 65.675,32.244 65.649,32.218 65.649,31.294 v2(65.999,30.944) ; 65.875,34.075 65.875,32.555 65.999,32.431 65.999,32.073 ; 66.375,34.825 66.375,32.814 66.854,32.335 ; 66.375,35.325 66.12,35.07 66.12,34.719 66.155,34.684 66.155,33.97 66.155,32.723 66.634,32.244 ; 66.625,34.714 66.625,33.208 67.52,32.313 67.52,30.227 68.321,29.425 70.516,29.425 ; 66.625,34.936 66.625,35.075 66.875,35.325 ; 66.875,34.825 66.875,34.075 66.875,33.269 67.74,32.404 67.74,30.318 68.412,29.645 70.607,29.645
  Top Layer w0.11: 56.657,28.898 56.73,28.825 60.735,28.825 62.1,30.19 62.1,34.075 ; 56.938,29.15 60.654,29.15 61.85,30.346 61.85,34.075 61.85,35.15 61.875,35.175 ; 58.066,29.495 60.595,29.495 61.605,30.505 61.605,34.075 ; v2(60.389,30.112) 60.422,30.112 61.375,31.065 61.375,34.075 ; 60.776,28.495 62.362,30.081 62.362,34.075 ; 61.545,28.065 61.545,28.845 62.625,29.925 62.625,34.075 ; 61.56,26.465 62.145,26.465 62.957,27.277 62.957,28.826 63.085,28.954 63.085,34.075 ; 61.56,27.24 62.115,27.24 62.747,27.872 62.747,28.913 62.875,29.041 62.875,34.075 62.875,34.825 ; 61.875,35.178 61.875,35.793 ; v2@62.375,36.25 62.375,36.825 ; v2@62.375,37.275 62.375,37.825 ; v2@62.875,36.75 62.875,37.325 ; 63.167,26.426 63.167,28.739 63.305,28.877 63.305,34.075 ; 63.377,25.821 63.377,28.652 63.515,28.79 63.515,34.075 ; 63.587,28.565 63.725,28.703 63.725,34.075 ; 63.797,27.389 64.457,28.048 64.457,29.066 64.154,29.369 64.154,34.075 ; 65.375,48.265 65.375,54.493 67.076,56.194 68.179,57.298 68.8,57.918 ; 65.63,48.575 65.63,54.198 69.225,57.793 ; 65.875,48.575 65.875,53.79 69.841,57.756 ; 66.115,47.085 66.375,46.825 ; 66.125,48.615 66.125,53.21 67.275,54.36 67.275,54.59 68.803,56.118 69.018,56.118 70.375,57.475 70.375,58.349 ; 66.375,47.325 66.375,52.65 67.75,54.025 67.75,54.538 68.909,55.697 69.051,55.697 70.976,57.622 70.976,58.076 ; v2(66.45,46.425) 66.475,46.425 66.875,46.825 ; 68.875,47.825 68.884,47.834 68.884,48.387 69.706,49.209 69.909,49.209 74.284,53.584 ; 69.582,48.575 69.831,48.824 70.025,48.824 74.476,53.275 ; 70.207,48.549 74.617,52.959 ; 70.78,47.932 75.008,52.16
  Top Layer w0.15: v2(59.989,37.734) v2(59.989,37.734) 60.264,37.736 60.353,37.825 60.375,37.825 ; v2(60.95,37.8) 60.971,37.779 61.307,37.779 61.353,37.825 61.375,37.825
  Bottom Layer w0.09: v2(44.43,41) 44.43,39.527 44.833,39.123 56.341,39.123 57.139,38.325 57.851,38.325 58.206,37.97 58.492,37.97 58.637,38.115 59.265,38.115 v2(59.475,38.325) ; 57.296,40 57.517,40 57.582,39.934 57.731,39.934 v2(57.79,39.875)
  Bottom Layer w0.1: v2(49.475,38.554) v2@49.475,38.632 ; v2@52.028,42.803 v2(52.031,42.8) ; 56.233,43.813 v2(57.782,43.813) ; 56.314,43.463 57.927,43.463 58.264,43.8 v2(58.85,43.8) ; 56.899,40.849 57.286,40.849 57.287,40.85 v2(57.79,40.85) ; 57.509,43.191 57.742,43.191 57.821,43.27 58.003,43.27 58.033,43.3 v2(58.348,43.3) ; 57.635,42.575 57.64,42.57 58.111,42.57 58.241,42.7 58.25,42.7 58.29,42.74 v2(58.875,42.74) ; 57.642,42.18 57.923,42.18 58.177,41.926 58.553,41.926 58.999,42.371 59.286,42.371 v2(59.29,42.375) ; 57.792,42.385 57.794,42.384 57.991,42.384 58.183,42.384 58.209,42.357 58.334,42.357 v2@58.391,42.3 ; 58.287,40.933 v2@58.858,40.933 ; 59.375,46.875 59.089,46.589 59.089,46.192 59.431,45.85 59.478,45.85 60.003,45.325 v2@60.375,45.325 ; v2(59.45,46.325) 59.441,46.334 59.441,46.616 59.55,46.725 59.575,46.75 ; v2(61.375,46.325) 61.375,48.53 66.362,53.518 ; 62.787,24.149 62.787,33.049 63.813,34.075 64.058,34.32 64.058,35.64 63.714,35.984 63.714,36.413 63.529,36.598 63.529,36.999 64.28,37.75 v2(64.8,37.75) ; 62.987,24.066 62.987,32.683 62.987,32.966 64.096,34.075 64.248,34.227 64.248,35.719 63.973,35.994 63.973,36.342 64.375,36.744 v2(64.375,37.35) ; 63.187,23.983 63.187,32.883 64.379,34.075 64.438,34.135 64.438,35.85 64.438,35.858 64.338,35.959 64.338,36.213 v2@64.375,36.25 ; 63.387,23.901 63.387,32.8 64.579,33.992 64.579,33.995 64.579,35.808 64.798,36.026 64.798,36.474 64.866,36.543 64.866,36.82 v2(64.875,36.829) ; 63.587,23.818 63.587,32.717 64.858,33.989 64.858,34.075 64.858,35.78 64.988,35.909 64.988,36.395 65.38,36.787 65.414,36.821 65.608,36.821 65.704,36.725 v2@65.775,36.725 ; 63.778,23.583 63.778,32.64 63.875,32.737 65.048,33.91 65.048,35.498 65.15,35.6 65.375,35.825 v2(65.375,36.24)
  Bottom Layer w0.11: 57.752,31.425 60.402,34.075 60.865,34.538 60.865,35.768 v2@61.335,36.239 ; 57.777,30.55 60.458,33.23 60.458,33.588 61.525,34.655 61.525,35.349 62.375,36.199 v2(62.375,36.24) ; 57.977,32.227 60.475,34.725 60.475,35.978 61.249,36.751 v2@61.872,36.751 ; 58.127,33.021 59.18,34.075 59.653,34.548 59.653,36.273 60.654,37.274 61.955,37.274 v2@62.374,37.274 ; 61.525,31.919 61.525,33.498 62.528,34.501 62.528,35.901 62.875,36.248 v2@62.875,36.75 ; 61.981,31.469 61.981,33.039 63.375,34.433 v2@63.375,36.25 ; v2(62.375,45.3) 62.375,45.848 62.045,46.178 61.906,46.317 61.906,48.34 67.341,53.775
  Bottom Layer w0.2: 69.826,34.72 69.88,34.72 ; 70.043,34.557 70.126,34.557
  other v2: 49.325,35.825 61.3,36.24 63.375,36.24 64.375,36.24 61.875,36.74 62.875,36.74 65.78,36.73 63.9,36.775 46.875,36.825 67.96,36.825 62.375,37.24 63.385,37.265 62.875,37.76 59.345,39.355 58.858,40.91 58.28,41.421 57.79,41.825 58.4,42.275 60.375,45.35

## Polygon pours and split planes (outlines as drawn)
5V_VIN on Signal Layer 2 "5V_VIN_L03_P084" (solid, remove dead copper, pour order 84): 11.599,49.324 12.825,50.55 31.375,50.55 31.975,49.95 31.975,32.6 31.375,32 14.15,31.99 11.599,34.541
GND on Signal Layer 2 "GND_L03_P088" (solid, remove dead copper, pour order 88): 0,79.6 120,79.6 120,0 0,0
VDDCPUGPU on Signal Layer 2 "VDDCPUGPU_L03_P001" (solid, remove dead copper, pour order 47): 65.475,38.3 65.05,37.875 62.623,37.877 62.5,38 62.5,38.66 62.05,39.156 62.05,43.95 61.1,44.9 61.1,46.65 60.675,47.075 59.75,47.075 51.75,55.075 28.95,55.075 28.45,55.575 28.45,59.1 28.975,59.625 55.45,59.625 65.475,49.6
VDDCORE on Signal Layer 2 "Signal Layer 2-VDDCORE" (solid, remove dead copper, pour order 54): 21.325,51.05 21.625,50.75 37.2,50.75 37.8,50.15 37.8,41.315 37.917,41.175 61.168,41.175 61.925,41.875 61.925,44.029 61.618,44.357 51.525,54.45 21.675,54.45 21.325,54.1
1V8 on Signal Layer 2 "1V8_L03_P001" (solid, remove dead copper, pour order 80): 55.548,59.725 65.973,49.3 81.2,49.3 81.65,49.75 81.65,55.9 80.05,57.5 76.75,57.5 72.625,61.625 18.425,61.625 9.75,52.95 9.75,33.075 12.4,30.425 29.025,30.425 29.3,30.7 29.3,34 29.175,34.125 28.525,34.125 28.35,33.95 28.35,32.225 27.925,31.8 13.95,31.8 11.4,34.35 11.4,51.7 19.425,59.725
3V3 on Signal Layer 2 "3V3_L03_P082" (solid, pour order 82): 20.3,27.625 20.025,27.35 20.025,25.825 20.275,25.575 20.975,25.575 23.675,22.875 32.375,14.175 46.525,14.175 47.125,14.775 47.125,20.05 46.275,20.9 31.22,20.9 24.592,27.625
5V_VIN on Signal Layer 2 "5V_VIN_L03_P087" (solid, pour order 87): 11.95,23.175 12.15,23.375 22.425,23.375 22.775,23.025 22.775,20.625 22.425,20.275 12.25,20.275 11.95,20.575
VDD2_DDR on Signal Layer 2 "Signal Layer 2-VDD2_DDR" (solid, remove dead copper, pour order 51): 89.985,49.081 66.351,49.081 66.016,48.719 66.016,45.106 65.429,44.426 65.429,36.41 67.6,34.239 67.6,28.2 67.344,27.944 34.294,27.944 33.85,27.5 33.85,24.3 34.296,23.854 78.57,23.846 87.968,33.244 90,33.244 90.157,33.401 90.157,48.909
VDDIO on Signal Layer 2 "VDDIO_L03_P001" (solid, remove dead copper, pour order 49): 62.352,37.952 62.172,37.772 60.085,37.772 37.8,37.772 37.8,41.038 61.524,41.038 62.352,40.21
GND on Top Layer "GND_L01_P086" (solid, remove dead copper, pour order 86): 0,79.797 120,79.797 120,0.197 0,0.197
VDDIO on Top Layer "VDDIO_L01_P062" (solid, pour order 62): 38.05,41.025 39.575,41.025 39.775,40.825 39.775,23.8 37.975,22 32.975,22 20.875,34.1 20.875,36.15 21,36.275 21.65,36.275 21.875,36.5 21.875,36.875 22,37 22.275,37 22.375,36.9 22.375,36.425 22.325,36.375 22.325,34.7 22.5,34.525 22.85,34.525 33.65,23.725 37.225,23.725 37.8,24.3 37.8,40.775
5V_VIN on Top Layer "5V_VIN_L01_P073" (solid, remove dead copper, pour order 73): 22.044,39.244 22.219,39.419 23.363,39.419 23.361,39.294 23.361,38.361 22.975,37.975 21.096,37.975 20.936,38.135 20.936,39.135 21.044,39.244
5V_VIN on Top Layer "5V_VIN_L01_P085" (solid, pour order 85): 11.95,46 12.25,46.3 13.5,46.3 13.825,45.975 13.825,23.7 13.825,21 13.55,20.725 12.125,20.725 11.95,20.9
VDD2_DDR on Top Layer "VDD2_DDR" (solid, remove dead copper, pour order 60): 37.7,24.375 37.175,23.85 34.3,23.85 33.851,24.299 33.851,40.599 33.7,40.75 32.095,40.75 31.95,40.903 31.95,42.739 32.111,42.9 37.4,42.9 37.7,42.6
NetL3_1 on Top Layer "NETL3_1_L01_P058" (solid, remove dead copper, pour order 58): 26.761,44.11 26.573,43.922 26.573,43.438 26.57,43.441 26.38,43.441 26.38,44.285 27.434,45.339 28.263,45.339 28.6,45.66 28.6,46.1 28.65,46.15 30.4,46.15 30.45,46.1 30.45,45.339 29.259,44.11
NetL5_1 on Top Layer "NETL5_1_L01_P061" (solid, remove dead copper, pour order 61): 31.131,42.671 29.896,42.671 28.098,40.873 28.157,40.814 30.286,40.814 31.131,40.814
NetL2_1 on Top Layer "NETL2_1_L01_P059" (solid, remove dead copper, pour order 59): 25.123,44.135 25.181,44.077 25.181,43.309 25.187,43.303 25.189,43.305 25.386,43.305 25.386,44.616 23.766,46.125 21.587,46.125 21.463,46.001 21.463,44.745 21.558,44.65 24.277,44.65 24.792,44.135
VDDCPUGPU on Top Layer "VDDCPUGPU_L01_P053" (solid, remove dead copper, pour order 53): 28.45,59.1 28.975,59.625 30.1,59.625 30.625,59.1 30.625,46.875 28.45,46.875
VDDCORE on Top Layer "VDDCORE_L01_P057" (solid, remove dead copper, pour order 57): 21.325,54.1 21.675,54.45 23.125,54.45 23.5,54.075 23.5,47.1 23.275,46.875 21.525,46.875 21.325,47.075
3V3 on Top Layer "3V3_AO_L01" (solid, pour order 65): 19.976,27.332 20.326,27.682 22.051,27.682 22.576,27.157 24.876,27.157 25.226,26.807 25.226,24.682 25.126,24.582 22.576,24.582 22.451,24.707 22.451,25.632 22.301,25.782 20.201,25.782 19.976,26.007
NetL4_1 on Top Layer "NetL8_1_L01" (solid, pour order 64): 24.948,22.129 20.973,22.135 20.926,22.182 20.926,22.607 21.001,22.678 22.447,22.678 22.601,22.832 22.601,23.682 22.726,23.807 25.076,23.807 25.226,23.657 25.226,22.407
5V_VIN on Top Layer "5V_VIN_L01_P074" (solid, pour order 74): 21.376,22.032 22.576,22.032 22.651,21.957 22.651,20.957 22.476,20.782 21.451,20.782 21.301,20.932 21.301,21.457 21.201,21.557 20.551,21.557 20.501,21.607 20.501,21.907 20.551,21.957 21.301,21.957
5V_VIN on Top Layer "5V_VIN_L01_P022" (solid, remove dead copper, pour order 67): 25.386,38.81 25.386,35.967 25.168,35.749 23.6,35.749 23.288,35.437 23.288,34.944 22.961,34.617 22.595,34.617 22.45,34.762 22.45,36.281 22.708,36.539 23.464,36.539 24.806,37.881 24.806,38.81
5V_VIN on Top Layer "5V_VIN_L01_P072" (solid, remove dead copper, pour order 72): 30.501,39.481 30.488,39.469 30.488,38.919 30.638,38.769 31.538,38.769 31.688,38.919 31.688,40.169 31.222,40.635 27.956,40.635 27.997,40.595 27.997,40.435 29.547,40.435
VDD1_DDR on Top Layer "VDD1_DDR_L01_P063" (solid, remove dead copper, pour order 63): 28.461,39.52 28.461,37.696 28.661,37.496 28.661,37.256 28.741,37.176 29.538,37.176 29.538,39.119 28.822,39.835 28.373,39.835 28.35,39.812 28.339,39.812 28.339,39.642
5V_VIN on Top Layer "5V_VIN_L01_P066" (solid, remove dead copper, pour order 66): 26.181,43.665 26.181,44.495 27.214,45.529 28.128,45.529 28.318,45.718 28.318,47.054 28.149,47.223 27.369,47.223 27.369,47.195 27.214,47.04 27.226,46.524 27.05,46.349 24.749,46.349 24.599,46.499 24.606,47.068 24.423,47.251 23.8,47.251 23.636,47.068 23.636,46.463 23.741,46.358 25.561,44.538 25.561,43.659 25.597,43.623 25.611,43.637 26.167,43.637 26.167,43.658 26.174,43.665
5V_VIN on Top Layer "5V_VIN_L01_P001" (solid, remove dead copper, pour order 68): 29.738,38.044 29.663,38.119 29.663,39.169 28.788,40.044 27.738,40.044 27.738,40.244 29.563,40.244 30.338,39.469 30.338,38.044
GND on Signal Layer 1 "GND_L02_P000" (solid, remove dead copper, pour order 0): 0,79.6 120,79.6 120,0 0,0
GND on Bottom Layer "GND_L04_P055" (solid, remove dead copper, pour order 55): 0,79.6 120,79.6 120,0 0,0

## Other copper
Top Layer:
  pour cut-out: 23.413,40.375 22.55,40.375 22.55,39.9 23.413,39.9
  pour cut-out: 21.338,40.119 20.988,40.119 20.988,39.369 21.338,39.369
  pour cut-out: 27.55,43.2 23.425,43.2 23.425,39.075 27.55,39.075
  pour cut-out: 17.901,23.582 20.901,23.582 20.926,23.557 20.926,20.582 17.926,20.582
  pour cut-out: 20.001,25.782 22.501,25.782 22.501,25.232 20.001,25.232
  pour cut-out: 20.638,50.644 20.638,48.15 21.288,48.15 21.288,50.644
  pour cut-out: 23.538,50.619 24.138,50.619 24.138,47.319 23.538,47.319
  pour cut-out: 24.688,47.119 27.138,47.119 27.138,46.519 27.088,46.569 24.688,46.569
  pour cut-out: 31.138,42.819 31.938,42.819 31.938,40.75 31.138,40.75
  pour cut-out: 32.413,39.394 32.413,40.65 31.663,40.65 31.663,39.394
  pour cut-out: 30.738,37.894 30.438,37.894 30.438,38.644 30.738,38.644
  pour cut-out: 27.488,35.619 28.088,35.019 29.988,35.019 29.988,35.119 29.688,35.419 28.188,35.419 27.988,35.619 27.988,36.019 26.038,36.019 26.038,35.219 25.338,35.219 25.288,35.269 25.288,35.669 23.588,35.669 23.438,35.519 23.438,35.369 24.638,35.369 25.138,35.369 25.138,35.119 25.388,34.869 26.188,34.869 26.188,35.169 26.638,35.619
  pour cut-out: 21.288,47.169 21.288,45.969 21.388,45.969 21.388,47.169
  pour cut-out: 30.488,47.069 30.488,46.069 30.638,46.069 30.638,47.069
  pour cut-out: 28.438,50.644 28.438,47.319 27.738,47.319 27.738,50.644
  pour cut-out: 27.738,36.919 28.338,36.919 28.338,36.769 27.738,36.769
  pour cut-out: 33.45,43.4 37.25,43.4 37.25,42.85 33.45,42.85
  pour cut-out: 20.988,39.319 20.738,39.319 20.588,39.169 20.588,38.019 20.888,38.019 20.988,38.119
  pour cut-out: 30.463,37.744 29.988,37.744 29.938,37.694 29.938,36.169 29.638,36.169 29.638,37.744 29.788,37.894 30.463,37.894
  pour cut-out: 30.663,50.619 30.663,48.219 31.313,48.219 31.313,50.619
  pour cut-out: 21.488,36.294 21.488,36.969 21.888,36.969 21.888,36.294
  pour cut-out: 19.288,36.294 19.288,36.969 19.688,36.969 19.688,36.294
  pour cut-out: 56.125,47.825 69.49,47.825 69.49,34.475 69.524,34.441 56.137,34.441
  pour cut-out: 67.469,46.428 67.537,46.496 69.625,46.496 74.724,51.594 87.59,51.594 90.709,48.476 90.709,33.404 86.764,29.459 74.76,29.459 67.404,36.815
  pour cut-out: 74.075,62 81.35,62 81.35,54.798 74.075,54.798
Bottom Layer:
  pour cut-out: 66.146,48.032 66.498,48.032 73.987,48.032 76.358,45.662 88.892,45.662 88.892,38.218 85.406,34.732 68.413,34.732 66.15,36.923

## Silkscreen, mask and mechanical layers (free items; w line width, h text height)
Top Overlay:
  text "J" at 27.26,70.556 h15
Drill Drawing:
  drawing of 190 lines, arcs and shapes, not listed
  text "PCB SPECIFICATIONS :" at -27.02,127.275 h3
  text "A.   MATERIAL :" at -27.02,123.275 h3
  text "FR-4" at 11.48,123.275 h3
  text "TG-170" at 27.98,123.275 h3
  text "X  TG-150" at 46.23,123.275 h3
  text "TG-140" at 62.23,123.275 h3
  text "B.   MATERIAL FAMILY :" at -27.02,120.275 h3
  text "N/A" at 11.48,120.275 h3
  text "C.   SOLDERMASK COLOR :" at -27.02,117.275 h3
  text "GREEN" at 11.48,117.275 h3
  text "X  BLUE" at 27.98,117.275 h3
  text "RED" at 46.23,117.275 h3
  text "BLACK" at 62.23,117.275 h3
  text "D.   SILKSCREEN COLOR :" at -27.02,114.275 h3
  text "X  WHITE" at 11.48,114.275 h3
  text "YELLOW" at 27.98,114.275 h3
  text "BLACK" at 46.23,114.275 h3
  text "PCB : TYPE 4" at 187.138,113.471 h3
  text "Layer" at 122.2,111.475 h2
  text "Name" at 130.567,111.475 h2
  text "Material" at 146.741,111.475 h2
  text "Thickness" at 161.275,111.475 h2
  text "Constant" at 173.215,111.475 h2
  text "E.   SURFACE FINISH :" at -27.02,111.275 h3
  text "X  ENIG" at 11.48,111.275 h3
  text "IMMERSION SILVER" at 27.98,111.275 h3
  text "IMMERSION TIN" at 62.23,111.275 h3
  text "HASL" at 11.48,108.275 h3
  text "HASL (PB-FREE)" at 27.98,108.275 h3
  text "GOLDEN FINGER" at 62.23,108.275 h3
  text "ASPECT-RATIO, AXE Z :" at 187.138,107.971 h3
  text "Top Overlay" at 130.567,107.475 h2
  text "F.   IMPEDANCE CONTROL :" at -27.02,105.275 h3
  text "NO" at 11.48,105.275 h3
  text "X  YES" at 27.98,105.275 h3
  text "Top Solder" at 130.567,103.475 h2
  text "Solder Resist" at 146.741,103.475 h2
  text "0,025mm" at 161.275,103.475 h2
  text "3.5" at 173.215,103.475 h2
  text "G.   THROUGH VIA :" at -27.02,102.275 h3
  text "PLUG THE VIAS WHICH ARE COVERED WITH SOLDERMASK ONE OR TWO SIDE." at 11.48,102.275 h3
  text "6 :1  to  8 :1 / LEVEL \"B\"" at 187.157,101.224 h3
  text "1" at 122.2,99.475 h2
  text "Top Layer" at 130.567,99.475 h2
  text "0,037mm" at 161.275,99.475 h2
  text "PLUG MATERIAL :" at 11.48,99.275 h3
  text "X  SOLDERMASK" at 36.98,99.275 h3
  text "NON-CONDUCTIVE EPOXY." at 62.23,99.275 h3
  text "H.   STACK-UP :" at -27.02,96.275 h3
  text "SEE LAYER STACK-UP SEQUENCE FOR OVERALL THICKNESS." at 11.48,96.275 h3
  text "Dielectric 1" at 130.567,95.475 h2
  text "0,070mm" at 161.275,95.475 h2
  text "3.8" at 173.215,95.475 h2
  text "2" at 122.199,91.475 h2
  text "Signal Layer 1" at 130.567,91.475 h2
  text "0,035mm" at 161.275,91.475 h2
  text "MINIMUN PARAMETERS" at 187.25,89.695 h3
  text "Dielectric 2" at 130.567,87.475 h2
  text "1,330mm" at 161.275,87.475 h2
  text "4.3" at 173.215,87.475 h2
  text "DEFAULT" at 187.25,84.195 h3
  text "3" at 122.2,83.475 h2
  text "Signal Layer 2" at 130.567,83.475 h2
  text "0,035mm" at 161.275,83.475 h2
  text "Dielectric 3" at 130.567,79.475 h2
  text "0,070mm" at 161.275,79.475 h2
  text "3.8" at 173.215,79.475 h2
  text "TRACKS : 0.100mm           / GAPS : 0.100mm" at 187.25,78.445 h3
  text "4" at 122.2,75.475 h2
  text "Bottom Layer" at 130.567,75.475 h2
  text "0,037mm" at 161.275,75.475 h2
  text "BGA :" at 187.225,73.62 h3
  text "Bottom Solder" at 130.567,71.475 h2
  text "Solder Resist" at 146.741,71.475 h2
  text "0,025mm" at 161.275,71.475 h2
  text "3.5" at 173.215,71.475 h2
  text "TRACKS : 0.090mm           / GAPS : 0.090mm" at 187.225,67.87 h3
  text "Bottom Overlay" at 130.567,67.475 h2
  text "Symbol" at 108.266,-14.385 h2.4
  text "Count" at 117.663,-14.385 h2.4
  text "Hole Size" at 127.407,-14.385 h2.4
  text "Plated" at 138.82,-14.385 h2.4
  text "Hole Type" at 147.073,-14.385 h2.4
  text "Drill Layer Pair" at 159.082,-14.385 h2.4
  text "Via/Pad" at 181.82,-14.385 h2.4
  text "Pad Shape" at 191.661,-14.385 h2.4
  text "Hole Length" at 204.521,-14.385 h2.4
  text "328" at 117.663,-18.525 h2
  text "0.200mm" at 127.407,-18.525 h2
  text "PTH" at 138.82,-18.525 h2
  text "Round" at 147.073,-18.525 h2
  text "Top Layer - Bottom Layer" at 159.082,-18.525 h2
  text "Via" at 181.82,-18.525 h2
  text "Rounded" at 191.661,-18.525 h2
  text "-" at 204.521,-18.525 h2
  text "D" at 107.478,-18.779 h1.84
  text "364" at 117.663,-22.665 h2
  text "0.350mm" at 127.407,-22.665 h2
  text "PTH" at 138.82,-22.665 h2
  text "Round" at 147.073,-22.665 h2
  text "Top Layer - Bottom Layer" at 159.082,-22.665 h2
  text "Via" at 181.82,-22.665 h2
  text "Rounded" at 191.661,-22.665 h2
  text "-" at 204.521,-22.665 h2
  text "C" at 107.478,-22.918 h1.84
  text "2" at 117.663,-26.804 h2
  text "0.500mm" at 127.407,-26.804 h2
  text "PTH" at 138.82,-26.804 h2
  text "Round" at 147.073,-26.804 h2
  text "Top Layer - Bottom Layer" at 159.082,-26.804 h2
  text "Pad" at 181.82,-26.804 h2
  text "Rounded" at 191.661,-26.804 h2
  text "-" at 204.521,-26.804 h2
  text "694 Total" at 117.663,-30.944 h2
